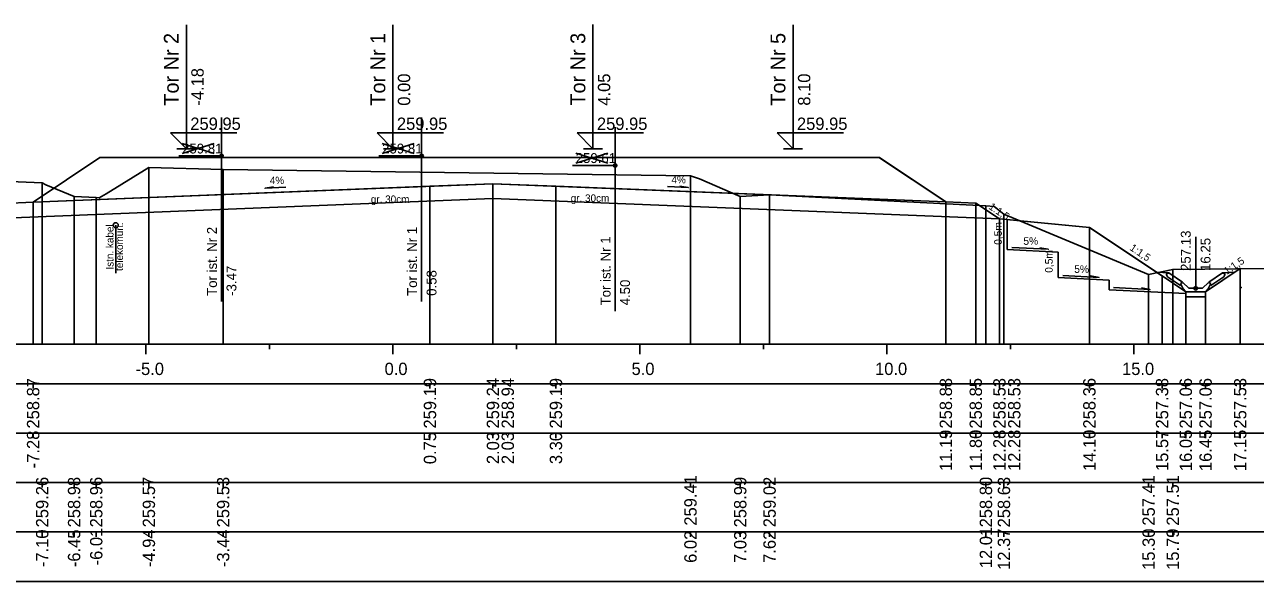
# Model space of a CAD drawing. Extents: x 6516023 to 6560129, y 5513077 to 5529206.
# Drawn here: x 6516396.01 to 6516420.92, y 5514501.31 to 5514512.57 of the extents above; entities that cross this region are included whole.
import ezdxf

# ---------------------------------------------------------------- set-up
doc = ezdxf.new("R2010")
doc.units = 0
for name, color, linetype in [('IR_default', 7, 'Continuous'), ('TOR_PRZEK_P-kable', 7, 'Continuous'), ('TOR_PRZEK_P-komponent', 7, 'Continuous'), ('TOR_PRZEK_P-odwodnienie', 7, 'Continuous'), ('TOR_PRZEK_P-opisy', 7, 'Continuous'), ('TOR_PRZEK_P-schodkowanie+wymiana', 7, 'Continuous'), ('TOR_PRZEK_P-tabelka istniejace', 7, 'Continuous'), ('TOR_PRZEK_P-tabelka projektowane', 7, 'Continuous'), ('TOR_PRZEK_P-teren istniejacy', 7, 'Continuous'), ('TOR_PRZEK_P-tory istniejace', 7, 'Continuous'), ('TOR_PRZEK_P-tory projektowane', 7, 'Continuous'), ('TOR_PRZEK_P-uklad odniesienia', 7, 'Continuous'), ('TOR_PRZEK_P-warstwa ochronna I', 7, 'Continuous'), ('TOR_PRZEK_P-warstwa ochronna II', 7, 'Continuous'), ('TOR_PS_T-skarpy projektowane', 7, 'Continuous')]:
    doc.layers.add(name, color=color, linetype=linetype)

msp = doc.modelspace()

# ---------------------------------------------------------------- linework, layer by layer
at = {"layer": 'IR_default'}
msp.add_lwpolyline([(6516395.581, 5514508.954), (6516396.178, 5514508.978), (6516396.18, 5514508.979), (6516397.531, 5514509.88), (6516397.531, 5514509.88), (6516398.071, 5514509.88), (6516398.072, 5514509.88), (6516399.281, 5514509.88), (6516399.281, 5514509.88), (6516401.031, 5514509.88), (6516401.389, 5514509.88), (6516401.713, 5514509.88), (6516403.463, 5514509.88), (6516403.464, 5514509.88), (6516405.213, 5514509.88), (6516405.213, 5514509.88), (6516405.763, 5514509.88), (6516405.765, 5514509.88), (6516407.513, 5514509.88), (6516407.515, 5514509.88), (6516409.263, 5514509.88), (6516409.264, 5514509.88), (6516409.813, 5514509.88), (6516409.819, 5514509.88), (6516413.313, 5514509.88), (6516413.317, 5514509.877), (6516414.657, 5514508.984), (6516414.658, 5514508.984), (6516415.263, 5514508.96), (6516415.265, 5514508.958), (6516415.742, 5514508.64), (6516415.747, 5514508.64), (6516417.563, 5514508.468), (6516419.029, 5514507.49), (6516419.035, 5514507.486), (6516419.513, 5514507.167), (6516419.515, 5514507.166), (6516419.914, 5514507.166), (6516419.915, 5514507.166), (6516420.616, 5514507.633)], dxfattribs=at)
at = {"layer": 'TOR_PRZEK_P-kable'}
msp.add_line((6516397.851, 5514508.513), (6516397.851, 5514507.539), dxfattribs=at)
msp.add_circle((6516397.851, 5514508.513), 0.05, dxfattribs=at)
at = {"layer": 'TOR_PRZEK_P-komponent'}
msp.add_lwpolyline([(6516397.531, 5514509.88), (6516399.281, 5514509.88), (6516398.071, 5514509.88), (6516401.031, 5514509.88), (6516401.713, 5514509.88), (6516403.463, 5514509.88), (6516405.213, 5514509.88), (6516405.763, 5514509.88), (6516407.513, 5514509.88), (6516409.263, 5514509.88), (6516409.813, 5514509.88), (6516413.313, 5514509.88), (6516414.657, 5514508.984), (6516405.488, 5514509.351), (6516396.178, 5514508.978)], close=True, dxfattribs=at)
at = {"layer": 'TOR_PRZEK_P-odwodnienie'}
for p, q in [((6516419.715, 5514507.236), (6516419.715, 5514508.28)), ((6516419.451, 5514507.362), (6516419.17, 5514507.549)), ((6516419.98, 5514507.362), (6516420.26, 5514507.549)), ((6516419.406, 5514507.295), (6516419.145, 5514507.469)), ((6516419.417, 5514507.312), (6516419.406, 5514507.295)), ((6516419.408, 5514507.331), (6516419.455, 5514507.355)), ((6516419.451, 5514507.362), (6516419.442, 5514507.349)), ((6516419.575, 5514507.236), (6516419.455, 5514507.355)), ((6516419.855, 5514507.236), (6516419.975, 5514507.355)), ((6516419.975, 5514507.355), (6516420.023, 5514507.331)), ((6516419.98, 5514507.362), (6516419.988, 5514507.349)), ((6516420.013, 5514507.312), (6516420.024, 5514507.295)), ((6516420.024, 5514507.295), (6516420.286, 5514507.469)), ((6516419.525, 5514507.166), (6516419.905, 5514507.166)), ((6516419.575, 5514507.236), (6516419.855, 5514507.236))]:
    msp.add_line(p, q, dxfattribs=at)
for points in [[(6516418.924, 5514507.56), (6516419.17, 5514507.549)], [(6516419.12, 5514507.522), (6516419.17, 5514507.549)], [(6516420.507, 5514507.56), (6516420.26, 5514507.549)], [(6516420.311, 5514507.522), (6516420.26, 5514507.549)], [(6516419.12, 5514507.522), (6516419.145, 5514507.469)], [(6516419.442, 5514507.349), (6516419.407, 5514507.331)], [(6516419.407, 5514507.331), (6516419.417, 5514507.312)], [(6516419.455, 5514507.236), (6516419.408, 5514507.331)], [(6516419.975, 5514507.236), (6516420.023, 5514507.331)], [(6516419.988, 5514507.349), (6516420.023, 5514507.331)], [(6516420.023, 5514507.331), (6516420.013, 5514507.312)], [(6516420.311, 5514507.522), (6516420.286, 5514507.469)], [(6516419.525, 5514507.166), (6516419.455, 5514507.236)], [(6516419.515, 5514507.166), (6516419.515, 5514507.166), (6516419.515, 5514507.166), (6516419.515, 5514507.165), (6516419.515, 5514507.166), (6516419.516, 5514507.165), (6516419.515, 5514507.166), (6516419.516, 5514507.166)], [(6516419.915, 5514507.166), (6516419.515, 5514507.166), (6516419.515, 5514507.066), (6516419.915, 5514507.066), (6516419.915, 5514507.166)], [(6516419.905, 5514507.166), (6516419.975, 5514507.236)], [(6516419.915, 5514507.166), (6516419.915, 5514507.166), (6516419.915, 5514507.166), (6516419.915, 5514507.165), (6516419.915, 5514507.166), (6516419.916, 5514507.165), (6516419.915, 5514507.166), (6516419.916, 5514507.166)], [(6516420.638, 5514507.252), (6516420.638, 5514507.252), (6516420.638, 5514507.252), (6516420.638, 5514507.251), (6516420.638, 5514507.252), (6516420.639, 5514507.251), (6516420.638, 5514507.252), (6516420.639, 5514507.252)]]:
    msp.add_lwpolyline(points, dxfattribs=at)
msp.add_circle((6516419.715, 5514507.236), 0.035, dxfattribs=at)
at = {"layer": 'TOR_PRZEK_P-opisy'}
for points in [[(6516401.294, 5514509.279), (6516400.876, 5514509.26), (6516401.044, 5514509.288)], [(6516409.024, 5514509.293), (6516409.442, 5514509.274), (6516409.274, 5514509.303)]]:
    msp.add_lwpolyline(points, dxfattribs=at)
at = {"layer": 'TOR_PRZEK_P-schodkowanie+wymiana'}
for p, q in [((6516415.901, 5514508.625), (6516415.901, 5514508.019)), ((6516415.901, 5514508.019), (6516416.931, 5514507.967)), ((6516416.931, 5514507.967), (6516416.931, 5514507.452)), ((6516416.931, 5514507.452), (6516417.961, 5514507.401)), ((6516417.961, 5514507.401), (6516417.961, 5514507.206)), ((6516417.961, 5514507.206), (6516419.515, 5514507.129))]:
    msp.add_line(p, q, dxfattribs=at)
at = {"layer": 'TOR_PRZEK_P-tabelka istniejace'}
for p, q in [((6516396.362, 5514503.206), (6516396.362, 5514503.306)), ((6516397.008, 5514503.206), (6516397.008, 5514503.306)), ((6516397.456, 5514503.206), (6516397.456, 5514503.306)), ((6516398.522, 5514503.206), (6516398.522, 5514503.306)), ((6516400.026, 5514503.206), (6516400.026, 5514503.306)), ((6516409.487, 5514503.206), (6516409.487, 5514503.306)), ((6516410.494, 5514503.206), (6516410.494, 5514503.306)), ((6516411.088, 5514503.206), (6516411.088, 5514503.306)), ((6516415.468, 5514503.206), (6516415.468, 5514503.306)), ((6516415.833, 5514503.206), (6516415.833, 5514503.306)), ((6516418.763, 5514503.206), (6516418.763, 5514503.306)), ((6516419.252, 5514503.206), (6516419.252, 5514503.306)), ((6516364.663, 5514502.306), (6516438.463, 5514502.306)), ((6516396.362, 5514502.206), (6516396.362, 5514502.306)), ((6516397.008, 5514502.206), (6516397.008, 5514502.306)), ((6516397.456, 5514502.206), (6516397.456, 5514502.306)), ((6516398.522, 5514502.206), (6516398.522, 5514502.306)), ((6516400.026, 5514502.206), (6516400.026, 5514502.306)), ((6516409.487, 5514502.206), (6516409.487, 5514502.306)), ((6516410.494, 5514502.206), (6516410.494, 5514502.306)), ((6516411.088, 5514502.206), (6516411.088, 5514502.306)), ((6516415.468, 5514502.206), (6516415.468, 5514502.306)), ((6516415.833, 5514502.206), (6516415.833, 5514502.306)), ((6516418.763, 5514502.206), (6516418.763, 5514502.306)), ((6516419.252, 5514502.206), (6516419.252, 5514502.306))]:
    msp.add_line(p, q, dxfattribs=at)
for points in [[(6516398.522, 5514509.679), (6516398.522, 5514506.306), (6516398.522, 5514506.176), (6516398.522, 5514506.106)], [(6516400.026, 5514509.638), (6516400.026, 5514506.306), (6516400.026, 5514506.176), (6516400.026, 5514506.106)], [(6516396.362, 5514509.368), (6516396.362, 5514506.306), (6516396.362, 5514506.176), (6516396.362, 5514506.106)], [(6516409.487, 5514509.512), (6516409.487, 5514506.306), (6516409.487, 5514506.176), (6516409.487, 5514506.106)], [(6516397.008, 5514509.09), (6516397.008, 5514506.306), (6516397.008, 5514506.176), (6516397.008, 5514506.106)], [(6516397.456, 5514509.07), (6516397.456, 5514506.306), (6516397.456, 5514506.176), (6516397.456, 5514506.106)], [(6516410.494, 5514509.095), (6516410.494, 5514506.306), (6516410.494, 5514506.176), (6516410.494, 5514506.106)], [(6516411.088, 5514509.124), (6516411.088, 5514506.306), (6516411.088, 5514506.176), (6516411.088, 5514506.106)], [(6516415.468, 5514508.905), (6516415.468, 5514506.306), (6516415.468, 5514506.176), (6516415.468, 5514506.106)], [(6516415.833, 5514508.737), (6516415.833, 5514506.306), (6516415.833, 5514506.176), (6516415.833, 5514506.106)], [(6516419.252, 5514507.619), (6516419.252, 5514506.306), (6516419.252, 5514506.176), (6516419.252, 5514506.106)], [(6516418.763, 5514507.517), (6516418.763, 5514506.306), (6516418.763, 5514506.176), (6516418.763, 5514506.106)]]:
    msp.add_lwpolyline(points, dxfattribs=at)
msp.add_lwpolyline([(6516364.663, 5514503.306), (6516364.663, 5514501.306), (6516438.463, 5514501.306), (6516438.463, 5514503.306)], close=True, dxfattribs=at)
at = {"layer": 'TOR_PRZEK_P-tabelka projektowane'}
for p, q in [((6516396.178, 5514505.206), (6516396.178, 5514505.306)), ((6516404.213, 5514505.206), (6516404.213, 5514505.306)), ((6516405.488, 5514505.206), (6516405.488, 5514505.306)), ((6516406.763, 5514505.206), (6516406.763, 5514505.306)), ((6516414.657, 5514505.206), (6516414.657, 5514505.306)), ((6516415.263, 5514505.206), (6516415.263, 5514505.306)), ((6516415.742, 5514505.206), (6516415.742, 5514505.306)), ((6516417.563, 5514505.206), (6516417.563, 5514505.306)), ((6516419.035, 5514505.206), (6516419.035, 5514505.306)), ((6516419.515, 5514505.206), (6516419.515, 5514505.306)), ((6516419.915, 5514505.206), (6516419.915, 5514505.306)), ((6516420.616, 5514505.206), (6516420.616, 5514505.306)), ((6516364.663, 5514504.306), (6516438.463, 5514504.306)), ((6516396.178, 5514504.206), (6516396.178, 5514504.306)), ((6516404.213, 5514504.206), (6516404.213, 5514504.306)), ((6516405.488, 5514504.206), (6516405.488, 5514504.306)), ((6516406.763, 5514504.206), (6516406.763, 5514504.306)), ((6516414.657, 5514504.206), (6516414.657, 5514504.306)), ((6516415.263, 5514504.206), (6516415.263, 5514504.306)), ((6516415.742, 5514504.206), (6516415.742, 5514504.306)), ((6516417.563, 5514504.206), (6516417.563, 5514504.306)), ((6516419.035, 5514504.206), (6516419.035, 5514504.306)), ((6516419.515, 5514504.206), (6516419.515, 5514504.306)), ((6516419.915, 5514504.206), (6516419.915, 5514504.306)), ((6516420.616, 5514504.206), (6516420.616, 5514504.306))]:
    msp.add_line(p, q, dxfattribs=at)
for points in [[(6516404.213, 5514509.3), (6516404.213, 5514506.306), (6516404.213, 5514506.176), (6516404.213, 5514506.106)], [(6516405.488, 5514509.351), (6516405.488, 5514506.306), (6516405.488, 5514506.176), (6516405.488, 5514506.106)], [(6516406.763, 5514509.3), (6516406.763, 5514506.306), (6516406.763, 5514506.176), (6516406.763, 5514506.106)], [(6516405.488, 5514509.051), (6516405.488, 5514506.306), (6516405.488, 5514506.176), (6516405.488, 5514506.106)], [(6516396.178, 5514508.978), (6516396.178, 5514506.306), (6516396.178, 5514506.176), (6516396.178, 5514506.106)], [(6516414.657, 5514508.984), (6516414.657, 5514506.306), (6516414.657, 5514506.176), (6516414.657, 5514506.106)], [(6516415.263, 5514508.96), (6516415.263, 5514506.306), (6516415.263, 5514506.176), (6516415.263, 5514506.106)], [(6516415.742, 5514508.64), (6516415.742, 5514506.306), (6516415.742, 5514506.176), (6516415.742, 5514506.106)], [(6516417.563, 5514508.468), (6516417.563, 5514506.306), (6516417.563, 5514506.176), (6516417.563, 5514506.106)], [(6516420.616, 5514507.633), (6516420.616, 5514506.306), (6516420.616, 5514506.176), (6516420.616, 5514506.106)], [(6516419.035, 5514507.486), (6516419.035, 5514506.306), (6516419.035, 5514506.176), (6516419.035, 5514506.106)], [(6516419.515, 5514507.166), (6516419.515, 5514506.306), (6516419.515, 5514506.176), (6516419.515, 5514506.106)], [(6516419.915, 5514507.166), (6516419.915, 5514506.306), (6516419.915, 5514506.176), (6516419.915, 5514506.106)]]:
    msp.add_lwpolyline(points, dxfattribs=at)
msp.add_lwpolyline([(6516364.663, 5514505.306), (6516364.663, 5514503.306), (6516438.463, 5514503.306), (6516438.463, 5514505.306)], close=True, dxfattribs=at)
at = {"layer": 'TOR_PRZEK_P-teren istniejacy'}
msp.add_lwpolyline([(6516393.258, 5514509.498), (6516396.362, 5514509.368), (6516396.434, 5514509.332), (6516397.008, 5514509.09), (6516397.456, 5514509.07), (6516397.517, 5514509.065), (6516397.658, 5514509.15), (6516398.522, 5514509.679), (6516400.026, 5514509.638), (6516409.487, 5514509.512), (6516409.672, 5514509.448), (6516410.494, 5514509.095), (6516411.088, 5514509.124), (6516415.468, 5514508.905), (6516415.638, 5514508.893), (6516415.833, 5514508.737), (6516418.763, 5514507.517), (6516419.252, 5514507.619), (6516421.188, 5514507.639)], dxfattribs=at)
at = {"layer": 'TOR_PRZEK_P-tory istniejace'}
for p, q in [((6516399.994, 5514510.688), (6516399.994, 5514506.968)), ((6516404.044, 5514510.688), (6516404.044, 5514506.968)), ((6516407.962, 5514510.495), (6516407.962, 5514506.775)), ((6516399.194, 5514509.96), (6516399.846, 5514510.163)), ((6516399.194, 5514510.163), (6516399.846, 5514509.96)), ((6516403.245, 5514509.96), (6516403.896, 5514510.163)), ((6516403.245, 5514510.163), (6516403.896, 5514509.96)), ((6516399.994, 5514509.913), (6516399.128, 5514509.913)), ((6516404.045, 5514509.913), (6516403.179, 5514509.913)), ((6516407.163, 5514509.767), (6516407.815, 5514509.97)), ((6516407.163, 5514509.97), (6516407.815, 5514509.767)), ((6516407.963, 5514509.72), (6516407.097, 5514509.72))]:
    msp.add_line(p, q, dxfattribs=at)
for centre in [(6516399.994, 5514509.913), (6516404.045, 5514509.913), (6516407.963, 5514509.72)]:
    msp.add_circle(centre, 0.035, dxfattribs=at)
at = {"layer": 'TOR_PRZEK_P-tory projektowane'}
for p, q in [((6516399.281, 5514510.937), (6516399.281, 5514512.569)), ((6516403.463, 5514510.937), (6516403.463, 5514512.569)), ((6516407.513, 5514510.938), (6516407.513, 5514512.57)), ((6516411.563, 5514510.937), (6516411.563, 5514512.569)), ((6516399.281, 5514510.937), (6516399.281, 5514510.06)), ((6516403.463, 5514510.937), (6516403.463, 5514510.06)), ((6516407.513, 5514510.938), (6516407.513, 5514510.06)), ((6516411.563, 5514510.937), (6516411.563, 5514510.06)), ((6516399.281, 5514510.06), (6516398.961, 5514510.379)), ((6516398.961, 5514510.379), (6516400.306, 5514510.379)), ((6516403.463, 5514510.06), (6516403.144, 5514510.379)), ((6516403.144, 5514510.379), (6516404.488, 5514510.379)), ((6516407.513, 5514510.06), (6516407.194, 5514510.379)), ((6516407.194, 5514510.379), (6516408.538, 5514510.379)), ((6516411.563, 5514510.06), (6516411.244, 5514510.379)), ((6516411.244, 5514510.379), (6516412.588, 5514510.379)), ((6516399.089, 5514510.06), (6516399.472, 5514510.06)), ((6516403.271, 5514510.06), (6516403.655, 5514510.06)), ((6516407.321, 5514510.06), (6516407.705, 5514510.06)), ((6516411.371, 5514510.06), (6516411.755, 5514510.06))]:
    msp.add_line(p, q, dxfattribs=at)
at = {"layer": 'TOR_PRZEK_P-uklad odniesienia'}
for p, q in [((6516368.463, 5514506.106), (6516438.463, 5514506.106)), ((6516398.463, 5514505.906), (6516398.463, 5514506.106)), ((6516400.963, 5514506.006), (6516400.963, 5514506.106)), ((6516403.463, 5514505.906), (6516403.463, 5514506.106)), ((6516405.963, 5514506.006), (6516405.963, 5514506.106)), ((6516408.463, 5514505.906), (6516408.463, 5514506.106)), ((6516410.963, 5514506.006), (6516410.963, 5514506.106)), ((6516413.463, 5514505.906), (6516413.463, 5514506.106)), ((6516415.963, 5514506.006), (6516415.963, 5514506.106)), ((6516418.463, 5514505.906), (6516418.463, 5514506.106))]:
    msp.add_line(p, q, dxfattribs=at)
at = {"layer": 'TOR_PRZEK_P-warstwa ochronna I'}
msp.add_lwpolyline([(6516395.102, 5514508.635), (6516405.488, 5514509.051), (6516415.742, 5514508.64)], dxfattribs=at)
at = {"layer": 'TOR_PRZEK_P-warstwa ochronna II'}
msp.add_lwpolyline([(6516382.789, 5514507.297), (6516385.588, 5514507.165), (6516386.206, 5514506.753), (6516386.956, 5514506.753), (6516387.361, 5514507.023), (6516389.281, 5514508.302), (6516395.102, 5514508.635), (6516395.581, 5514508.954), (6516396.178, 5514508.978), (6516404.213, 5514509.3), (6516405.488, 5514509.351), (6516406.763, 5514509.3), (6516414.657, 5514508.984), (6516415.263, 5514508.96), (6516415.742, 5514508.64), (6516417.563, 5514508.468), (6516419.035, 5514507.486), (6516419.515, 5514507.166), (6516419.915, 5514507.166), (6516420.616, 5514507.633)], dxfattribs=at)
at = {"layer": 'TOR_PS_T-skarpy projektowane'}
for points in [[(6516415.994, 5514508.063), (6516416.73, 5514508.024), (6516416.557, 5514508.055)], [(6516417.024, 5514507.497), (6516417.76, 5514507.457), (6516417.587, 5514507.488)], [(6516418.054, 5514507.251), (6516418.79, 5514507.211), (6516418.617, 5514507.242)]]:
    msp.add_lwpolyline(points, dxfattribs=at)

# ---------------------------------------------------------------- texts
at = {"layer": 'TOR_PRZEK_P-kable'}
for s, height, p in [('telekomun.', 0.15, (6516398, 5514507.587)), ('Istn. kabel', 0.14999, (6516397.806, 5514507.615))]:
    msp.add_text(s, height=height, rotation=90.0511, dxfattribs=at).set_placement(p)
at = {"layer": 'TOR_PRZEK_P-odwodnienie'}
for s, p in [('257.13', (6516419.615, 5514507.586)), ('16.25', (6516420.015, 5514507.586))]:
    msp.add_text(s, height=0.2, rotation=90, dxfattribs=at).set_placement(p)
at = {"layer": 'TOR_PRZEK_P-opisy'}
for s, rotation, p in [('4%', 0.1515, (6516400.971, 5514509.344)), ('4%', 359.8485, (6516409.103, 5514509.359)), ('1:1,5', 325.9299, (6516415.512, 5514508.853)), ('1:1,5', 325.9299, (6516418.367, 5514508.021)), ('1:1,5', 34.0701, (6516420.348, 5514507.506))]:
    msp.add_text(s, height=0.15, rotation=rotation, dxfattribs=at).set_placement(p)
at = {"layer": 'TOR_PRZEK_P-schodkowanie+wymiana'}
for p in [(6516415.79, 5514508.115), (6516416.82, 5514507.549)]:
    msp.add_text('0,5m', height=0.1545, rotation=90, dxfattribs=at).set_placement(p)
at = {"layer": 'TOR_PRZEK_P-tabelka istniejace'}
for s, p in [('259.26', (6516396.487, 5514502.398)), ('258.98', (6516397.133, 5514502.398)), ('258.96', (6516397.581, 5514502.398)), ('259.57', (6516398.647, 5514502.398)), ('259.53', (6516400.151, 5514502.398)), ('259.41', (6516409.612, 5514502.433)), ('258.99', (6516410.619, 5514502.398)), ('259.02', (6516411.213, 5514502.4)), ('258.80', (6516415.593, 5514502.398)), ('258.63', (6516415.958, 5514502.398)), ('257.41', (6516418.888, 5514502.433)), ('257.51', (6516419.377, 5514502.433)), ('-7.10', (6516396.487, 5514501.594)), ('-6.45', (6516397.133, 5514501.593)), ('-6.01', (6516397.581, 5514501.629)), ('-4.94', (6516398.647, 5514501.595)), ('-3.44', (6516400.151, 5514501.595)), ('6.02', (6516409.612, 5514501.68)), ('7.03', (6516410.619, 5514501.678)), ('7.62', (6516411.213, 5514501.68)), ('12.01', (6516415.593, 5514501.573)), ('12.37', (6516415.958, 5514501.538)), ('15.30', (6516418.888, 5514501.538)), ('15.79', (6516419.377, 5514501.538))]:
    msp.add_text(s, height=0.25, rotation=90, dxfattribs=at).set_placement(p)
at = {"layer": 'TOR_PRZEK_P-tabelka projektowane'}
for s, p in [('258.87', (6516396.303, 5514504.398)), ('259.19', (6516404.338, 5514504.398)), ('259.24', (6516405.613, 5514504.399)), ('258.94', (6516405.913, 5514504.399)), ('259.19', (6516406.888, 5514504.398)), ('258.88', (6516414.782, 5514504.398)), ('258.85', (6516415.388, 5514504.397)), ('258.53', (6516415.867, 5514504.398)), ('258.53', (6516416.167, 5514504.398)), ('258.36', (6516417.688, 5514504.398)), ('257.38', (6516419.16, 5514504.398)), ('257.06', (6516419.64, 5514504.398)), ('257.06', (6516420.04, 5514504.398)), ('257.53', (6516420.741, 5514504.398)), ('-7.28', (6516396.303, 5514503.594)), ('0.75', (6516404.338, 5514503.677)), ('2.03', (6516405.613, 5514503.678)), ('2.03', (6516405.913, 5514503.678)), ('3.30', (6516406.888, 5514503.678)), ('11.19', (6516414.782, 5514503.538)), ('11.80', (6516415.388, 5514503.538)), ('12.28', (6516415.867, 5514503.538)), ('12.28', (6516416.167, 5514503.538)), ('14.10', (6516417.688, 5514503.538)), ('15.57', (6516419.16, 5514503.538)), ('16.05', (6516419.64, 5514503.537)), ('16.45', (6516420.04, 5514503.537)), ('17.15', (6516420.741, 5514503.537))]:
    msp.add_text(s, height=0.25, rotation=90, dxfattribs=at).set_placement(p)
at = {"layer": 'TOR_PRZEK_P-tory istniejace'}
for s, p in [('259.81', (6516399.194, 5514509.963)), ('259.81', (6516403.245, 5514509.963)), ('259.61', (6516407.163, 5514509.77))]:
    msp.add_text(s, height=0.2, dxfattribs=at).set_placement(p)
for s, rotation, p in [('Tor ist. Nr 2', 90.0511, (6516399.9, 5514507.082)), ('Tor ist. Nr 1', 90.0511, (6516403.951, 5514507.082)), ('Tor ist. Nr 1', 90.0511, (6516407.869, 5514506.889)), ('-3.47', 90, (6516400.294, 5514507.083)), ('0.58', 90, (6516404.345, 5514507.083)), ('4.50', 90, (6516408.263, 5514506.89))]:
    msp.add_text(s, height=0.2, rotation=rotation, dxfattribs=at).set_placement(p)
at = {"layer": 'TOR_PRZEK_P-tory projektowane'}
for s, height, p in [('Tor Nr 2', 0.3, (6516399.126, 5514510.931)), ('Tor Nr 1', 0.3, (6516403.308, 5514510.931)), ('Tor Nr 3', 0.3, (6516407.358, 5514510.932)), ('Tor Nr 5', 0.3, (6516411.408, 5514510.931)), ('-4.18', 0.25, (6516399.631, 5514510.93)), ('0.00', 0.25, (6516403.813, 5514510.93)), ('4.05', 0.25, (6516407.863, 5514510.93)), ('8.10', 0.25, (6516411.913, 5514510.93))]:
    msp.add_text(s, height=height, rotation=90, dxfattribs=at).set_placement(p)
for p in [(6516399.361, 5514510.44), (6516403.543, 5514510.44), (6516407.593, 5514510.44), (6516411.643, 5514510.44)]:
    msp.add_text('259.95', height=0.25, dxfattribs=at).set_placement(p)
at = {"layer": 'TOR_PRZEK_P-uklad odniesienia'}
for s, p in [('-5.0', (6516398.252, 5514505.481)), ('0.0', (6516403.294, 5514505.481)), ('5.0', (6516408.294, 5514505.481)), ('10.0', (6516413.224, 5514505.481)), ('15.0', (6516418.224, 5514505.481))]:
    msp.add_text(s, height=0.25, dxfattribs=at).set_placement(p)
at = {"layer": 'TOR_PRZEK_P-warstwa ochronna I'}
for p in [(6516403.016, 5514508.964), (6516407.063, 5514508.985)]:
    msp.add_text('gr. 30cm', height=0.15, dxfattribs=at).set_placement(p)
at = {"layer": 'TOR_PS_T-skarpy projektowane'}
for p in [(6516416.227, 5514508.115), (6516417.257, 5514507.548)]:
    msp.add_text('5%', height=0.1545, dxfattribs=at).set_placement(p)

doc.saveas('drawing.dxf')
